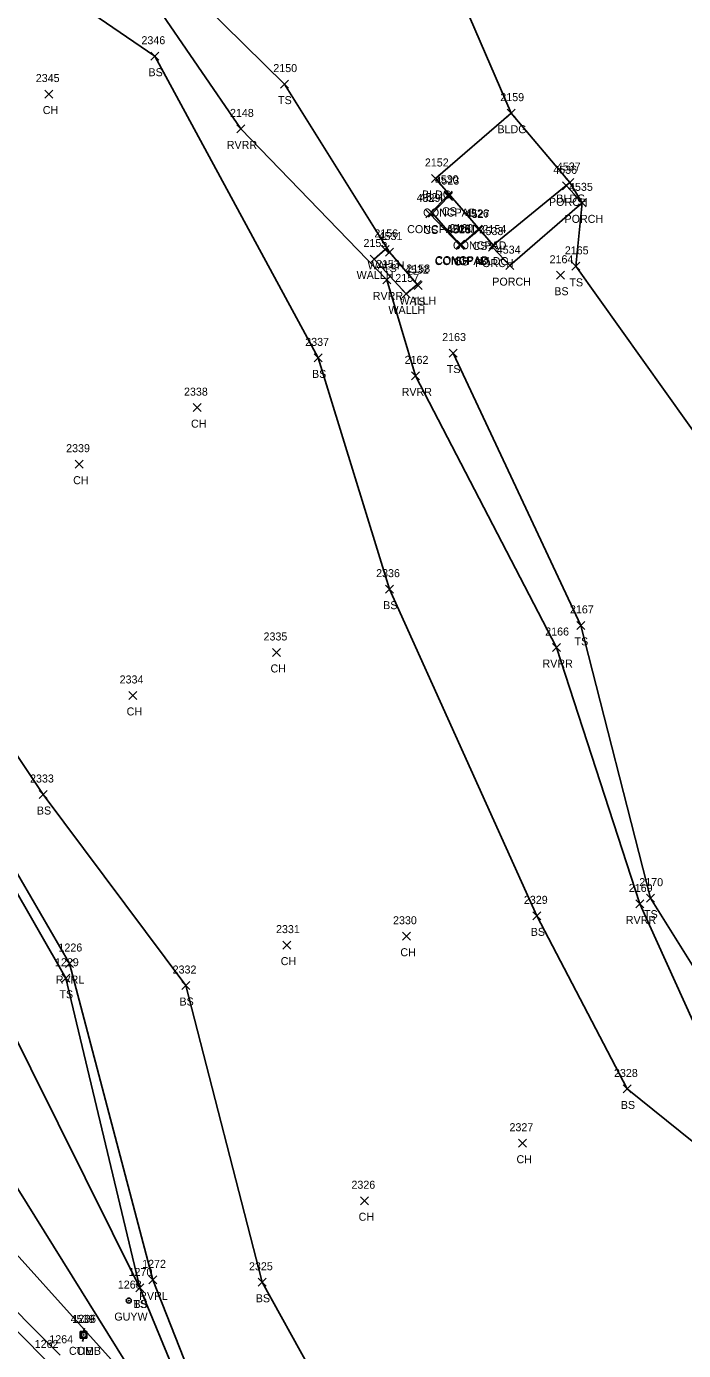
# Model space of a CAD drawing. Extents: x 1509053 to 1511576, y 400838 to 402572.
# Drawn here: x 1509710.5 to 1509874.8, y 401904.1 to 402235 of the extents above; entities that cross this region are included whole.
import ezdxf

# ---------------------------------------------------------------- set-up
doc = ezdxf.new("R2010")
doc.units = 0
for name, color, linetype in [('C_A', 7, 'Continuous'), ('C_I', 7, 'Continuous'), ('CBP', 7, 'Continuous'), ('D_A', 7, 'Continuous'), ('D_I', 7, 'Continuous'), ('D_TIC', 7, 'Continuous'), ('DHW', 7, 'Continuous'), ('L_A', 7, 'Continuous'), ('L_I', 7, 'Continuous'), ('L_TIC', 7, 'Continuous'), ('LAWA', 7, 'Continuous'), ('LAWE', 7, 'Continuous'), ('LBC', 7, 'Continuous'), ('LBF', 7, 'Continuous'), ('LELB', 7, 'Continuous'), ('LS', 7, 'Continuous'), ('LSOGP', 7, 'Continuous'), ('P_I', 7, 'Continuous'), ('PET', 7, 'Continuous'), ('R_I', 7, 'Continuous'), ('U_A', 7, 'Continuous'), ('U_I', 7, 'Continuous'), ('UP', 7, 'Continuous'), ('UPGW', 7, 'Continuous')]:
    doc.layers.add(name, color=color, linetype=linetype)

msp = doc.modelspace()

# ---------------------------------------------------------------- linework, layer by layer
at = {"layer": 'CBP'}
for radius in [0.625, 0.0833]:
    msp.add_circle((1509724.83, 401907.98), radius, dxfattribs=at)
at = {"layer": 'D_TIC'}
for points in [[(1509796.45, 402175.92), (1509798.44, 402177.92)], [(1509798.44, 402175.92), (1509796.45, 402177.92)], [(1509799.2, 402178.32), (1509801.2, 402180.32)], [(1509801.2, 402178.32), (1509799.2, 402180.32)], [(1509807.15, 402169.54), (1509809.15, 402171.54)], [(1509809.15, 402169.54), (1509807.15, 402171.54)], [(1509804.39, 402167.2), (1509806.39, 402169.2)], [(1509806.39, 402167.2), (1509804.39, 402169.2)]]:
    msp.add_lwpolyline(points, dxfattribs=at)
at = {"layer": 'DHW'}
for points in [[(1509797.45, 402176.92), (1509800.2, 402179.32)], [(1509805.39, 402168.2), (1509797.45, 402176.92)], [(1509805.39, 402168.2), (1509808.15, 402170.54)]]:
    msp.add_lwpolyline(points, dxfattribs=at)
at = {"layer": 'L_TIC'}
for points in [[(1509741.57, 402226.61), (1509743.56, 402228.61)], [(1509743.56, 402226.61), (1509741.57, 402228.61)], [(1509773.99, 402219.64), (1509775.99, 402221.64)], [(1509775.99, 402219.64), (1509773.99, 402221.64)], [(1509715.1, 402217.15), (1509717.1, 402219.15)], [(1509717.1, 402217.15), (1509715.1, 402219.15)], [(1509830.65, 402212.37), (1509832.65, 402214.37)], [(1509832.65, 402212.37), (1509830.65, 402214.37)], [(1509763.07, 402208.44), (1509765.07, 402210.44)], [(1509765.07, 402208.44), (1509763.07, 402210.44)], [(1509811.79, 402196.05), (1509813.79, 402198.05)], [(1509813.79, 402196.05), (1509811.79, 402198.05)], [(1509811.79, 402196.05), (1509813.79, 402198.05)], [(1509813.79, 402196.05), (1509811.79, 402198.05)], [(1509814.92, 402191.86), (1509816.92, 402193.86)], [(1509816.92, 402191.86), (1509814.92, 402193.86)], [(1509844.5, 402194.21), (1509846.5, 402196.21)], [(1509846.5, 402194.21), (1509844.5, 402196.21)], [(1509845.35, 402195.04), (1509847.35, 402197.04)], [(1509847.35, 402195.04), (1509845.35, 402197.04)], [(1509815, 402191.54), (1509817, 402193.54)], [(1509817, 402191.54), (1509815, 402193.54)], [(1509848.39, 402189.96), (1509850.39, 402191.96)], [(1509850.39, 402189.96), (1509848.39, 402191.96)], [(1509810.3, 402187.19), (1509812.3, 402189.19)], [(1509812.3, 402187.19), (1509810.3, 402189.19)], [(1509811.02, 402187.39), (1509813.02, 402189.39)], [(1509813.02, 402187.39), (1509811.02, 402189.39)], [(1509822.46, 402183.34), (1509824.46, 402185.34)], [(1509824.46, 402183.34), (1509822.46, 402185.34)], [(1509822.57, 402183.18), (1509824.57, 402185.18)], [(1509824.57, 402183.18), (1509822.57, 402185.18)], [(1509817.91, 402179.4), (1509819.91, 402181.4)], [(1509819.91, 402179.4), (1509817.91, 402181.4)], [(1509817.91, 402179.31), (1509819.91, 402181.31)], [(1509819.91, 402179.31), (1509817.91, 402181.31)], [(1509818.04, 402179.63), (1509820.04, 402181.63)], [(1509820.04, 402179.63), (1509818.04, 402181.63)], [(1509818.17, 402179.52), (1509820.17, 402181.52)], [(1509820.17, 402179.52), (1509818.17, 402181.52)], [(1509826.02, 402178.9), (1509828.02, 402180.9)], [(1509828.02, 402178.9), (1509826.02, 402180.9)], [(1509826.2, 402179.4), (1509828.2, 402181.4)], [(1509828.2, 402179.4), (1509826.2, 402181.4)], [(1509800.24, 402177.66), (1509802.24, 402179.66)], [(1509802.24, 402177.66), (1509800.24, 402179.66)], [(1509830.33, 402174.26), (1509832.33, 402176.26)], [(1509832.33, 402174.26), (1509830.33, 402176.26)], [(1509846.82, 402174.09), (1509848.82, 402176.09)], [(1509848.82, 402174.09), (1509846.82, 402176.09)], [(1509799.56, 402170.69), (1509801.56, 402172.69)], [(1509801.56, 402170.69), (1509799.56, 402172.69)], [(1509807.41, 402169.27), (1509809.41, 402171.27)], [(1509809.41, 402169.27), (1509807.41, 402171.27)], [(1509843.01, 402171.86), (1509845.01, 402173.86)], [(1509845.01, 402171.86), (1509843.01, 402173.86)], [(1509816.17, 402152.41), (1509818.17, 402154.41)], [(1509818.17, 402152.41), (1509816.17, 402154.41)], [(1509782.45, 402151.2), (1509784.45, 402153.2)], [(1509784.45, 402151.2), (1509782.45, 402153.2)], [(1509806.78, 402146.71), (1509808.78, 402148.71)], [(1509808.78, 402146.71), (1509806.78, 402148.71)], [(1509752.15, 402138.76), (1509754.15, 402140.76)], [(1509754.15, 402138.76), (1509752.15, 402140.76)], [(1509722.69, 402124.63), (1509724.69, 402126.63)], [(1509724.69, 402124.63), (1509722.69, 402126.63)], [(1509800.23, 402093.39), (1509802.23, 402095.39)], [(1509802.23, 402093.39), (1509800.23, 402095.39)], [(1509848.1, 402084.34), (1509850.1, 402086.34)], [(1509850.1, 402084.34), (1509848.1, 402086.34)], [(1509772.03, 402077.57), (1509774.03, 402079.57)], [(1509774.03, 402077.57), (1509772.03, 402079.57)], [(1509841.98, 402078.8), (1509843.98, 402080.8)], [(1509843.98, 402078.8), (1509841.98, 402080.8)], [(1509736.06, 402066.82), (1509738.06, 402068.82)], [(1509738.06, 402066.82), (1509736.06, 402068.82)], [(1509713.67, 402042.06), (1509715.67, 402044.06)], [(1509715.67, 402042.06), (1509713.67, 402044.06)], [(1509862.82, 402014.71), (1509864.82, 402016.71)], [(1509864.82, 402014.71), (1509862.82, 402016.71)], [(1509865.47, 402016.15), (1509867.47, 402018.15)], [(1509867.47, 402016.15), (1509865.47, 402018.15)], [(1509837.12, 402011.73), (1509839.12, 402013.73)], [(1509839.12, 402011.73), (1509837.12, 402013.73)], [(1509804.48, 402006.63), (1509806.48, 402008.63)], [(1509806.48, 402006.63), (1509804.48, 402008.63)], [(1509774.58, 402004.41), (1509776.58, 402006.41)], [(1509776.58, 402004.41), (1509774.58, 402006.41)], [(1509720.26, 401999.81), (1509722.26, 402001.81)], [(1509722.26, 401999.81), (1509720.26, 402001.81)], [(1509719.34, 401996.13), (1509721.34, 401998.13)], [(1509721.34, 401996.13), (1509719.34, 401998.13)], [(1509749.31, 401994.31), (1509751.31, 401996.31)], [(1509751.31, 401994.31), (1509749.31, 401996.31)], [(1509859.63, 401968.45), (1509861.63, 401970.45)], [(1509861.63, 401968.45), (1509859.63, 401970.45)], [(1509833.51, 401954.89), (1509835.51, 401956.89)], [(1509835.51, 401954.89), (1509833.51, 401956.89)], [(1509794.05, 401940.51), (1509796.05, 401942.51)], [(1509796.05, 401940.51), (1509794.05, 401942.51)], [(1509741.13, 401920.74), (1509743.13, 401922.74)], [(1509743.13, 401920.74), (1509741.13, 401922.74)], [(1509737.82, 401918.7), (1509739.82, 401920.7)], [(1509739.82, 401918.7), (1509737.82, 401920.7)], [(1509737.82, 401918.7), (1509739.82, 401920.7)], [(1509739.82, 401918.7), (1509737.82, 401920.7)], [(1509768.39, 401920.13), (1509770.39, 401922.13)], [(1509770.39, 401920.13), (1509768.39, 401922.13)]]:
    msp.add_lwpolyline(points, dxfattribs=at)
at = {"layer": 'LAWA'}
msp.add_lwpolyline([(1509076.57, 402183.15), (1509127.79, 402182.33), (1509173.6, 402169.45), (1509206.41, 402183.98), (1509219.47, 402177.73), (1509276.12, 402165.35), (1509324.31, 402150.34), (1509333.92, 402141.66), (1509378.2, 402140.76), (1509422.99, 402135.87), (1509484.22, 402126.37), (1509536.38, 402111.03), (1509587.67, 402075.95), (1509623.1, 402040.21), (1509661.3, 402001.82), (1509687.76, 401950.54), (1509742.09, 401890.27)], dxfattribs=at)
at = {"layer": 'LAWE'}
for points in [[(1509123.74, 402492.84), (1509257.15, 402479.28), (1509295.46, 402474.2), (1509323.52, 402463.27), (1509340.74, 402459.51), (1509387.7, 402446.48), (1509437.74, 402415.48), (1509460.68, 402397.47), (1509520.56, 402367.88), (1509582.65, 402355.05), (1509635.23, 402334.07), (1509671.33, 402306.45), (1509693.48, 402289.28), (1509731.88, 402256.56), (1509764.07, 402209.44), (1509800.56, 402171.69), (1509807.78, 402147.71), (1509842.98, 402079.8), (1509863.82, 402015.71), (1509885.9, 401967.01)], [(1509105.87, 402324.24), (1509166.85, 402316.84), (1509211.49, 402305.13), (1509268.21, 402284.91), (1509312.96, 402259.07), (1509356.2, 402241.45), (1509401.11, 402232.66), (1509452.56, 402212.8), (1509514.16, 402192.04), (1509556.38, 402176.06), (1509631.87, 402126.97), (1509661.73, 402089.31), (1509701.86, 402034.14), (1509721.26, 402000.81), (1509742.13, 401921.74), (1509766.75, 401859.14), (1509782.51, 401819.75), (1509797.91, 401768.02), (1509814.1, 401723.17), (1509831.98, 401671.21)]]:
    msp.add_lwpolyline(points, dxfattribs=at)
at = {"layer": 'LBC'}
for points in [[(1509812.79, 402197.05), (1509831.65, 402213.38), (1509846.35, 402196.04)], [(1509812.79, 402197.05), (1509827.2, 402180.4)], [(1509846.35, 402196.04), (1509827.2, 402180.4)]]:
    msp.add_lwpolyline(points, dxfattribs=at)
at = {"layer": 'LBF'}
msp.add_lwpolyline([(1509827.02, 402179.9), (1509831.33, 402175.26), (1509849.39, 402190.96), (1509845.5, 402195.21)], dxfattribs=at)
at = {"layer": 'LELB'}
for points in [[(1510159.39, 401957.43), (1510109.97, 401933.78), (1510073.83, 401925.83), (1510030.04, 401920.72), (1509978.38, 401922.31), (1509938.9, 401925.26), (1509910.2, 401929.61), (1509860.63, 401969.45), (1509838.12, 402012.73), (1509801.23, 402094.39), (1509783.45, 402152.2), (1509742.56, 402227.61), (1509676.33, 402272.85), (1509632.84, 402314.37), (1509578.95, 402339.23), (1509514.2, 402355.92), (1509451.14, 402377.68), (1509400.45, 402407.85), (1509346.01, 402449.55), (1509331.23, 402458.28), (1509283.72, 402454.96), (1509188.27, 402469.29), (1509186.96, 402469.12), (1509142.12, 402468.65)], [(1509342.35, 402460.5), (1509388.98, 402451.84), (1509438.42, 402417.91), (1509462.47, 402401.71), (1509520.99, 402370.94), (1509584.16, 402359.65), (1509637.85, 402336.46), (1509671.92, 402311.04), (1509696.29, 402294.18), (1509734.49, 402260.5), (1509774.99, 402220.64)], [(1509893.6, 401622.33), (1509860.64, 401660.7), (1509835.46, 401719.88), (1509820.45, 401775.67), (1509804.55, 401821.18), (1509793.58, 401877.47), (1509769.39, 401921.13), (1509750.31, 401995.31), (1509714.67, 402043.06), (1509675.87, 402101.28), (1509636.96, 402136.16), (1509603.47, 402183.37), (1509565.38, 402200.63), (1509506.19, 402219.72), (1509454.31, 402229.61), (1509409.3, 402242.42), (1509343.87, 402268.78), (1509286.85, 402299.31), (1509229.32, 402329.05), (1509168.38, 402334.88), (1509111.42, 402354.71)], [(1509268.21, 402284.91), (1509314.49, 402254.64), (1509356.98, 402231.85), (1509402.27, 402223.46), (1509451.09, 402207.68), (1509510.53, 402186.04), (1509553.53, 402174.63), (1509629.32, 402126.51), (1509658.3, 402084.82), (1509698.84, 402034.54), (1509720.34, 401997.13), (1509738.81, 401919.7), (1509762.85, 401861.64), (1509780.24, 401817.03), (1509795.72, 401767.1), (1509811.96, 401722.66)], [(1509801.24, 402178.66), (1509774.99, 402220.64)], [(1509823.57, 402184.18), (1509818.91, 402180.31), (1509811.3, 402188.19), (1509815.92, 402192.86)], [(1509801.24, 402178.66), (1509808.41, 402170.27)], [(1509386.28, 402168.51), (1509440.17, 402176.72), (1509501.07, 402173.56), (1509547.44, 402149.69), (1509608.94, 402102.89), (1509648.8, 402068.27), (1509684.12, 402026.81), (1509704.75, 401988.35), (1509738.81, 401919.7)], [(1509847.82, 402175.09), (1509886.95, 402120.34), (1509907.05, 402022.55), (1509918.73, 401987.4), (1509928.84, 401979.54), (1509935.79, 401973.56), (1509945.59, 401973.04), (1509961.46, 401977.52), (1509972.96, 401975.8), (1510014.35, 401976.24), (1510035.33, 401975.1)], [(1509817.17, 402153.41), (1509849.1, 402085.34), (1509866.47, 402017.15), (1509882.78, 401991.11), (1509898.34, 401984.87), (1509903.47, 401976.22), (1509914.35, 401974.68), (1509914.19, 401956.28)], [(1509361.47, 402094.85), (1509410.83, 402081.54), (1509459.37, 402065.34), (1509506.44, 402045.45), (1509552.07, 402021.06), (1509595.83, 401996.62), (1509639.75, 401971.21), (1509681.43, 401940.52), (1509718.97, 401902.89)], [(1509673.68, 402014.35), (1509694.66, 401966.31), (1509742.09, 401890.27)]]:
    msp.add_lwpolyline(points, dxfattribs=at)
at = {"layer": 'LS'}
msp.add_lwpolyline([(1509816, 402192.54), (1509812.02, 402188.39), (1509818.91, 402180.4), (1509823.46, 402184.34)], dxfattribs=at)
at = {"layer": 'LSOGP'}
msp.add_lwpolyline([(1509886.95, 402120.34), (1509847.82, 402175.09), (1509849.39, 402190.96), (1509846.35, 402196.04), (1509831.65, 402213.38), (1509810.8, 402261.62), (1509829.53, 402284.86), (1509786.94, 402318.01), (1509741.81, 402353.02), (1509703.97, 402366.5), (1509663.58, 402377.9), (1509601.4, 402398.68), (1509540.06, 402426.11), (1509501.59, 402438.85), (1509479.41, 402463.89), (1509474.2, 402464.72), (1509459.59, 402484.75), (1509407.76, 402498.88)], dxfattribs=at)
at = {"layer": 'PET'}
msp.add_lwpolyline([(1509715.31, 401901.72), (1509679, 401938.37)], dxfattribs=at)
at = {"layer": 'UP'}
for p, q in [((1509725, 401909.65), (1509724.75, 401908.82)), ((1509723.91, 401907.15), (1509723.91, 401908.82)), ((1509723.91, 401908.82), (1509725.58, 401908.82)), ((1509725.58, 401907.15), (1509723.91, 401907.15)), ((1509724.5, 401906.32), (1509724.75, 401907.15)), ((1509724.75, 401907.99), (1509724.75, 401907.99)), ((1509725.58, 401908.82), (1509725.58, 401907.15))]:
    msp.add_line(p, q, dxfattribs=at)
msp.add_circle((1509724.75, 401907.99), 0.833, dxfattribs=at)
at = {"layer": 'UPGW'}
for radius in [0.625, 0.0833]:
    msp.add_circle((1509736.09, 401916.55), radius, dxfattribs=at)

# ---------------------------------------------------------------- texts
at = {"layer": 'C_A'}
msp.add_text('TIE', height=2, dxfattribs=at).set_placement((1509722.91, 401902.98))
at = {"layer": 'C_I'}
msp.add_text('4539', height=2, dxfattribs=at).set_placement((1509721.56, 401910.98))
at = {"layer": 'D_A'}
for p in [(1509795.79, 402174.32), (1509793.04, 402171.92), (1509803.74, 402165.54), (1509800.98, 402163.2)]:
    msp.add_text('WALLH', height=2, dxfattribs=at).set_placement(p)
at = {"layer": 'D_I'}
for s, p in [('2156', (1509797.46, 402182.32)), ('2155', (1509794.75, 402179.92)), ('2158', (1509805.46, 402173.54)), ('2157', (1509802.7, 402171.2))]:
    msp.add_text(s, height=2, dxfattribs=at).set_placement(p)
at = {"layer": 'L_A'}
for s, p in [('BS', (1509741.01, 402222.61)), ('TS', (1509773.4, 402215.64)), ('CH', (1509714.59, 402213.15)), ('BLDG', (1509828.24, 402208.37)), ('RVRR', (1509760.58, 402204.44)), ('BLDG', (1509809.38, 402192.05)), ('BLDG', (1509809.38, 402192.05)), ('PORCH', (1509841.12, 402190.21)), ('BLDG', (1509842.94, 402191.04)), ('CONCPAD', (1509809.65, 402187.54)), ('CS', (1509814.36, 402187.86)), ('PORCH', (1509845.01, 402185.96)), ('CONCPAD', (1509805.67, 402183.39)), ('CS', (1509809.74, 402183.19)), ('CONCPAD', (1509817.11, 402179.34)), ('CS', (1509822.01, 402179.18)), ('CONCPAD', (1509812.56, 402175.4)), ('CONCPAD', (1509812.69, 402175.63)), ('CS', (1509817.35, 402175.31)), ('SH', (1509817.66, 402175.52)), ('BLDG', (1509823.79, 402175.4)), ('TS', (1509799.65, 402173.66)), ('PORCH', (1509822.64, 402174.9)), ('PORCH', (1509826.95, 402170.26)), ('TS', (1509846.23, 402170.08)), ('RVRR', (1509797.08, 402166.69)), ('BS', (1509842.45, 402167.86)), ('TS', (1509806.82, 402165.27)), ('BS', (1509781.89, 402147.2)), ('TS', (1509815.58, 402148.41)), ('RVRR', (1509804.3, 402142.71)), ('CH', (1509751.64, 402134.76)), ('CH', (1509722.18, 402120.63)), ('BS', (1509799.67, 402089.39)), ('TS', (1509847.51, 402080.34)), ('CH', (1509771.52, 402073.57)), ('RVRR', (1509839.49, 402074.8)), ('CH', (1509735.55, 402062.82)), ('BS', (1509713.11, 402038.06)), ('RVRR', (1509860.33, 402010.71)), ('TS', (1509864.88, 402012.15)), ('BS', (1509836.56, 402007.73)), ('CH', (1509774.07, 402000.41)), ('CH', (1509803.97, 402002.63)), ('RVRL', (1509717.83, 401995.81)), ('TS', (1509718.75, 401992.13)), ('BS', (1509748.75, 401990.31)), ('BS', (1509859.07, 401964.45)), ('CH', (1509833, 401950.89)), ('CH', (1509793.54, 401936.51)), ('TS', (1509737.22, 401914.7)), ('BS', (1509737.26, 401914.7)), ('RVRL', (1509738.69, 401916.74)), ('BS', (1509767.83, 401916.13))]:
    msp.add_text(s, height=2, dxfattribs=at).set_placement(p)
at = {"layer": 'L_I'}
for s, p in [('2346', (1509739.25, 402230.61)), ('2150', (1509772.21, 402223.64)), ('2345', (1509712.84, 402221.15)), ('2159', (1509828.95, 402216.38)), ('2148', (1509761.38, 402212.44)), ('2152', (1509810.1, 402200.05)), ('2152', (1509810.1, 402200.05)), ('4537', (1509843.09, 402199.04)), ('4530', (1509812.57, 402195.86)), ('4523', (1509812.74, 402195.54)), ('4536', (1509842.19, 402198.21)), ('4535', (1509846.13, 402193.96)), ('4529', (1509808.03, 402191.19)), ('4524', (1509808.76, 402191.39)), ('4526', (1509820.15, 402187.34)), ('4527', (1509820.31, 402187.18)), ('4525', (1509815.65, 402183.4)), ('4528', (1509815.65, 402183.31)), ('2160', (1509816.22, 402183.63)), ('2161', (1509817, 402183.52)), ('4533', (1509823.76, 402182.9)), ('2154', (1509824.51, 402183.41)), ('4531', (1509798.55, 402181.66)), ('4534', (1509828.07, 402178.26)), ('2164', (1509841.27, 402175.86)), ('2165', (1509845.08, 402178.08)), ('2153', (1509797.87, 402174.69)), ('4532', (1509805.15, 402173.27)), ('2163', (1509814.43, 402156.41)), ('2337', (1509780.19, 402155.2)), ('2162', (1509805.04, 402150.71)), ('2338', (1509749.89, 402142.76)), ('2339', (1509720.43, 402128.63)), ('2336', (1509797.91, 402097.39)), ('2167', (1509846.36, 402088.34)), ('2166', (1509840.18, 402082.8)), ('2335', (1509769.77, 402081.57)), ('2334', (1509733.8, 402070.82)), ('2333', (1509711.41, 402046.06)), ('2170', (1509863.69, 402020.15)), ('2169', (1509861.07, 402018.71)), ('2329', (1509834.85, 402015.73)), ('2330', (1509802.14, 402010.63)), ('2331', (1509772.89, 402008.41)), ('1226', (1509718.51, 402003.81)), ('1229', (1509717.64, 402000.13)), ('2332', (1509747.05, 401998.31)), ('2328', (1509857.37, 401972.45)), ('2327', (1509831.25, 401958.89)), ('2326', (1509791.74, 401944.51)), ('1272', (1509739.43, 401924.74)), ('2325', (1509766.13, 401924.13)), ('1270', (1509736.04, 401922.7)), ('1270', (1509736.04, 401922.7)), ('1264', (1509716.22, 401905.89))]:
    msp.add_text(s, height=2, dxfattribs=at).set_placement(p)
at = {"layer": 'P_I'}
msp.add_text('1262', height=2, dxfattribs=at).set_placement((1509712.57, 401904.72))
at = {"layer": 'R_I'}
msp.add_text('1264', height=2, dxfattribs=at).set_placement((1509716.22, 401905.89))
at = {"layer": 'U_A'}
for s, p in [('GUYW', (1509732.48, 401911.55)), ('COMB', (1509721.13, 401902.99))]:
    msp.add_text(s, height=2, dxfattribs=at).set_placement(p)
at = {"layer": 'U_I'}
for s, p in [('1268', (1509733.35, 401919.55)), ('1266', (1509721.95, 401910.99))]:
    msp.add_text(s, height=2, dxfattribs=at).set_placement(p)

doc.saveas('drawing.dxf')
